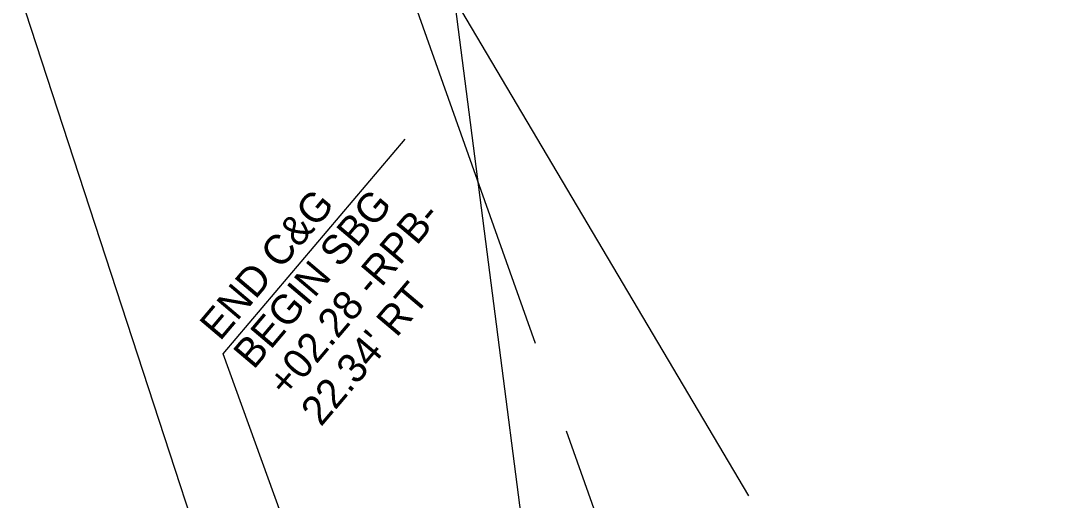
# Model space of a CAD drawing. Extents: x 1761082 to 1764358, y 421907 to 425434.
# Drawn here: x 1762629.6 to 1762805.2, y 423773.7 to 423855.3 of the extents above; entities that cross this region are included whole.
import ezdxf

# ---------------------------------------------------------------- set-up
doc = ezdxf.new("R2010")
doc.units = 0
for name, color, linetype in [('MARK UTURN ARROW CELL', 7, 'Continuous'), ('Prop Mkg Solid White Diagonals', 7, 'Continuous'), ('Prop Mkg Solid White Lane Line', 7, 'Continuous'), ('Prop Mkg Solid Yel Skip LT', 7, 'Continuous'), ('Prop Mkg Solid Yel Skip RT', 7, 'Continuous'), ('Scratch_Level_0', 7, 'Continuous'), ('Scratch_Level_1', 7, 'Continuous')]:
    doc.layers.add(name, color=color, linetype=linetype)

msp = doc.modelspace()

# ---------------------------------------------------------------- linework, layer by layer
at = {"layer": 'MARK UTURN ARROW CELL'}
for points in [[(1762717.14, 423800.32), (1762686.66, 423886.31), (1762769.46, 423984.05)], [(1762684.86, 423690.18), (1762629.61, 423859.52), (1762714.68, 423959.94)], [(1762753.43, 423774.41), (1762701.14, 423862.74), (1762774.59, 423949.45)], [(1762738.34, 423740.53), (1762722.42, 423785.44)]]:
    msp.add_lwpolyline(points, dxfattribs=at)
at = {"layer": 'Prop Mkg Solid White Diagonals'}
msp.add_arc((1763611.44, 423125.64), 999, 138.81963, 144.27858, dxfattribs=at)
at = {"layer": 'Prop Mkg Solid White Lane Line'}
msp.add_arc((1763611.44, 423125.64), 999, 138.81963, 144.27858, dxfattribs=at)
at = {"layer": 'Prop Mkg Solid Yel Skip RT'}
msp.add_lwpolyline([(1762696.78, 423708.06), (1762664.07, 423798.6), (1762695, 423835.12)], dxfattribs=at)
at = {"layer": 'Scratch_Level_0'}
msp.add_arc((1763611.44, 423125.64), 1000, 138.81963, 143.93371, dxfattribs=at)
at = {"layer": 'Scratch_Level_1'}
msp.add_lwpolyline([(1762725.19, 423689.75), (1762700.56, 423881.1), (1762754, 423944.18)], dxfattribs=at)

# ---------------------------------------------------------------- texts
at = {"layer": 'Prop Mkg Solid Yel Skip LT'}
for s, p in [('END C&G', (1762663.5, 423800.62)), ('BEGIN SBG', (1762669.22, 423795.77)), ('+02.28 -RPB-', (1762674.95, 423790.92)), ("22.34' RT", (1762680.67, 423786.07))]:
    msp.add_text(s, height=5, rotation=49.7301, dxfattribs=at).set_placement(p)

doc.saveas('drawing.dxf')
